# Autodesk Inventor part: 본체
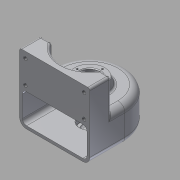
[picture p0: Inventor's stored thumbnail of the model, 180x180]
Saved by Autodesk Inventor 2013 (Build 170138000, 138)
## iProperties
Created: 2015-02
Part Number: 본체
Material: 알루미늄 6061
Document SubType Name: Modeling
Designer: Administrator
Density: 2.71 g/cm^3
Mass: 575.525 g
Surface Area: 706.56 cm^2
Volume: 212.371 cm^3
Author: Administrator
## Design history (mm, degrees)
sketch "스케치1"
  geometry: L1 (-50, 0)-(-50, -50); L2 (50, 0)-(50, -50); L3 (-50, -50)-(50, -50); A1 r 50 centre (0, 0) between (50, 0) and (-50, 0); 1 further point
  constraints: 6 end point, 2 point on circle, 2 tangent, 1 centre point, 1 coincident, 1 parallel, 1 perpendicular, 1 vertical
  dimensions: "d0" = 100 diameter of A1; "d1" = 50 distance from line of L3 point (0, 0)
extrude "돌출1" new body sketch "스케치1" distance "d2" = 50; taper "d3" = 0 deg
feature "쉘1" dims "d4" = 4
sketch "스케치3"
  geometry: L1 (0, 4)-(0, 46) reference; L2 (0, 0)-(0, 50) reference; L3 (50, 50)-(0, 50) reference; L4 (0, 50)-(-50, 50) reference; L5 (0, 50)-(0, 60); L6 (0, 60)-(-21.36, 60); L7 (-21.36, 60)-(-25, 50); L8 (0, 0)-(0, -9); L9 (0, -9)-(-20, -9); L10 (-20, -9)-(-20, 0); L11 (-20, 0)-(0, 0)
  constraints: 14 end point, 6 perpendicular, 1 midpoint
  dimensions: "d5" = 10 distance of L2.end L5.end; "d6" = 110 deg angle of L4 L7; "d7" = 50 diameter of L7.end L5; "d9" = 9 distance of L2.start L8.end; "d10" = 40 diameter of L10 L8
revolve "회전2" stored, may be unused: angle "d11" = 90 deg
sketch "스케치6"
  geometry: L1 (100, 0)-(0, 0) reference; L2 (100, 0)-(100, 50) reference; L3 (0, 50)-(100, 50) reference; L4 (0, 0)-(0, 50) reference; L5 (0, 0)-(0, 95); L6 (0, 95)-(100, 95); L7 (100, 95)-(100, 0); 1 further point
  constraints: 6 end point, 1 collinear, 1 parallel, 1 perpendicular
  dimensions: "d52" = 95 distance of L1.end L5.end
extrude "돌출2" join sketch "스케치6" distance "d53" = 30; taper "d54" = 0 deg
sketch "스케치7"
  geometry: L1 (-50, -20)-(50, -20) reference; L2 (50, 0)-(50, -20) reference; L3 (-50, -20)-(-50, 0) reference; L4 (-50, -50)-(-50, -20) reference; L5 (50, -50)-(-50, -50) reference; L6 (50, -20)-(50, -50) reference; L7 (-50, -20)-(50, -20) reference; L8 (34.641, -20)-(-34.641, -20); A1 r 50 centre (0, 0) between (50, 0) and (-50, 0) reference; A2 r 40 centre (0, 0) between (-34.641, -20) and (34.641, -20); A3 r 50 centre (0, 0) between (50, 0) and (-50, 0) reference; 1 further point
  constraints: 2 end point, 2 point on circle, 1 centre point, 1 coincident, 1 collinear, 1 point on line
  dimensions: "d55" = 80 diameter of A2
extrude "돌출3" cut sketch "스케치7" stored distance "d56" = 30; taper "d57" = 0 deg
sketch "스케치8"
  geometry: L1 (100, 95)-(0, 95) reference; L2 (0, 0)-(0, 95) reference; 5 further points
  constraints: 2 horizontal alignment, 2 vertical alignment
  dimensions: "d58" = 33 distance of point (91.75, 53) point (91.75, 86); "d60" = 9 distance from line of L1 point (91.75, 86); "d61" = 83.5 distance of point (8.25, 86) point (91.75, 86); "d62" = 8.25 distance from line of L2 point (8.25, 86)
hole "구멍5" sketch "스케치8" at (8.25, 86), (91.75, 86), (91.75, 53), (8.25, 53) diameter "d63" = 5.134; stored, may be unused: countersink angle "d67" = 90 deg, drill point angle "d69" = 118 deg; dims "d64" = 10, "d65" = 4, "d66" = 2, "d68" = 13
fillet "모깎기1" dims "d71" = 3
revolve "회전3" stored, may be unused: angle "d73" = 90 deg
hole "구멍6" diameter "d76" = 20; stored, may be unused: countersink angle "d80" = 90 deg, drill point angle "d82" = 0 deg; dims "d74" = 10, "d75" = 10, "d77" = 10, "d78" = 4, "d79" = 2, "d81" = 66
hole "구멍7" diameter "d85" = 28; stored, may be unused: countersink angle "d89" = 90 deg, drill point angle "d91" = 0 deg; dims "d83" = 10, "d84" = 10, "d86" = 10, "d87" = 4, "d88" = 2, "d90" = 10
hole "구멍8" diameter "d94" = 28; stored, may be unused: countersink angle "d98" = 90 deg, drill point angle "d100" = 0 deg; dims "d92" = 10, "d93" = 10, "d95" = 10, "d96" = 4, "d97" = 2, "d99" = 8
sketch "스케치9"
  geometry: C1 r 14 at (0, 0) reference; 1 further point
  constraints: 1 vertical alignment
  dimensions: "d101" = 18 distance of C1.centre point (0, 18)
hole "구멍9" sketch "스케치9" at (0, 18) diameter "d102" = 2.459; stored, may be unused: countersink angle "d106" = 90 deg, drill point angle "d108" = 118 deg; dims "d103" = 6, "d104" = 4, "d105" = 2, "d107" = 9
fillet "모깎기3" dims "d112" = 10
chamfer "모따기1" distance "d113" = 1; stored, may be unused: second distance "d114" = 2, angle "d115" = 45 deg
fillet "모깎기4" dims "d116" = 0.3
fillet "모깎기5" dims "d117" = 3
node "작업 평면3"
sketch "스케치10"
  geometry: L1 (40, 0)-(-40, 0) reference; 2 further points
  constraints: 1 vertical alignment, 1 other
  dimensions: "d118" = 25 distance from line of point (0, 25) L1
feature "엠보싱1" sketch "스케치10" dims "d5" = 10, "d6" = 110 deg, "d7" = 50, "d9" = 9, "d10" = 40, "d119" = 0.5, "d120" = 0
fillet "모깎기6" dims "d121" = 3
fillet "모깎기7" dims "d122" = 6
node "솔리드1"
pattern_circular "원형 패턴2" dims angle "d110" = 360 deg
node "절단 모서리 투영1"
